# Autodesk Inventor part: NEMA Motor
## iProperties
Author: Administrator
Shininess: 41.0
PropertySet Name: _Private Model Information
Created: 2001-01
Part Number: NEMA Motor
Document SubType Name: Modeling
Designer: Administrator
Control State: 0
Master: False
Checked Out: False
PropertySet Name: Design Tracking Control
Density: 0.0
Volumn: 0.0
Area: 0.0
PropertySet Name: Model Information
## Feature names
1. Extrusion1
2. Mirror1
3. Shell1
4. Revolution4
5. Revolution2
6. Revolution3
7. Fillet1
8. Extrusion2
9. Extrusion3
